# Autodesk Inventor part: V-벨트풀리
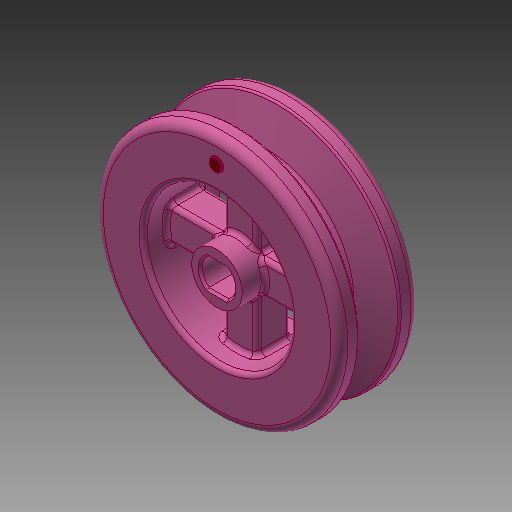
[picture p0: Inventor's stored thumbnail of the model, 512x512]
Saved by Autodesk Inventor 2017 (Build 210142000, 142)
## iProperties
Created: 2018-01
Part Number: V-벨트풀리
Material: 스테인리스강
Document SubType Name: Modeling
Designer: mduedu
Density: 8.08 g/cm^3
Mass: 210.967 g
Surface Area: 122.238 cm^2
Volume: 26.1098 cm^3
Appearance: 분홍색
Author: mduedu
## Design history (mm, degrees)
sketch "스케치1"
  geometry: C1 r 29 at (0, 0); 1 further point
  constraints: 1 centre point, 1 coincident
  dimensions: "d0" = 58 diameter of C1
extrude "돌출1" new body sketch "스케치1" stored distance "d1" = 19; taper "d2" = 0 deg
sketch "스케치2"
  geometry: L1 (29, -9.5)-(-29, -9.5) reference; L2 (-29, -9.5)-(-29, 9.5) reference; L3 (-29, 9.5)-(29, 9.5) reference; L4 (29, 9.5)-(29, -9.5) reference; L5 (-29, 0)-(29, 0); L6 (29, 4.825)-(20, 2.074); L7 (20, 2.074)-(20, -2.074); L8 (20, -2.074)-(29, -4.825); L9 (29, -4.825)-(29, 4.825); L10 (26.3, 9.5)-(26.3, -9.5); L11 (0, -13.3)-(0, 13.3) reference; 4 further points
  constraints: 12 end point, 9 point on line, 3 midpoint, 2 perpendicular, 1 collinear, 1 symmetric about line
  dimensions: "d3" = 34 deg angle of L8 L6; "d4" = 2.7 distance between parallel lines of L10 L4; "d5" = 6.3 distance between parallel lines of L7 L10; "d6" = 8 distance of point (26.3, -4) point (26.3, 4)
revolve "회전1" sketch "스케치2" stored, may be unused: angle "d7" = 90 deg
fillet "모깎기1" dims "d8" = 0.5
fillet "모깎기2" dims "d9" = 1
fillet "모깎기3" dims "d10" = 2
sketch "스케치3"
  geometry: C1 r 17.5 at (0, 0); 1 further point
  constraints: 1 centre point, 1 coincident
  dimensions: "d11" = 35 diameter of C1
extrude "돌출2" cut sketch "스케치3" stored distance "d12" = 19; taper "d13" = 0 deg
sketch "스케치4"
  geometry: C1 r 6 at (0, 0); 1 further point
  constraints: 1 centre point, 1 coincident
  dimensions: "d14" = 12 diameter of C1
extrude "돌출3" join sketch "스케치4" stored distance "d15" = 19; taper "d16" = 0 deg
sketch "스케치5"
  geometry: L1 (0, 6)-(0, 19); L2 (4, 4.472)-(4, 17.037); L3 (4.444, 19.5)-(4.444, 20.524); L4 (-4, 4.472)-(-4, 17.037); L5 (-4.444, 19.5)-(-4.444, 20.524); A1 r 6 centre (0, 0) between (0, 6) and (-4, 4.472) reference; A2 r 17.5 centre (0, 0) between (4, 17.037) and (-4, 17.037) reference; A3 r 20 centre (0, 0) between (4.444, 19.5) and (-4.444, 19.5) reference; 1 further point
  constraints: 10 end point, 7 point on circle, 4 parallel, 1 point on line, 1 vertical, 1 other
  dimensions: "d52" = 8 distance between parallel lines of L2 L4
extrude "돌출4" join sketch "스케치5" stored distance "d18" = 8; taper "d19" = 0 deg
fillet "모깎기4" dims "d20" = 1
fillet "모깎기5" dims "d24" = 1
fillet "모깎기6" dims "d25" = 1
hole "구멍1" diameter "d28" = 8; stored, may be unused: countersink angle "d32" = 90 deg, drill point angle "d34" = 118 deg; dims "d26" = 10, "d27" = 10, "d29" = 6, "d30" = 4, "d31" = 2, "d33" = 8
sketch "스케치6"
  geometry: L1 (-2.332, -3.25)-(2.332, -3.25); L2 (2.332, 3.25)-(-2.332, 3.25); L3 (-2.332, -3.25)-(2.332, 3.25); L4 (2.332, -3.25)-(-2.332, 3.25); A1 r 4 centre (0, 0) between (2.332, 3.25) and (-2.332, 3.25) reference; A2 r 4 centre (0, 0) between (2.332, 3.25) and (-2.332, 3.25); A3 r 4 centre (0, 0) between (-2.332, -3.25) and (2.332, -3.25); 1 further point
  constraints: 8 end point, 7 point on circle, 2 centre point, 2 coincident, 2 midpoint, 1 horizontal, 1 parallel
  dimensions: "d35" = 6.5 distance of L1.end L2.start
extrude "돌출5" join sketch "스케치6" stored distance "d37" = 8; taper "d38" = 0 deg
chamfer "모따기1" distance "d39" = 0.5; stored, may be unused: second distance "d40" = 2, angle "d41" = 45 deg
chamfer "모따기2" distance "d42" = 0.5; stored, may be unused: second distance "d43" = 2, angle "d44" = 45 deg
sketch "스케치7" dims "d45" = 47
  geometry: C1 r 1.5 at (0, 23.5); 2 further points
  constraints: 2 vertical alignment, 1 centre point, 1 coincident, 2 other
  dimensions: "d46" = 3 diameter of C1
extrude "돌출6" join sketch "스케치7" distance "d47" = 0.5; taper "d48" = 0 deg
fillet "모깎기7" dims "d49" = 0.1
node "솔리드1"
pattern_circular "원형 패턴1" dims angle "d22" = 360 deg
node "절단 모서리 투영1"
node "절단 모서리 투영2"
other parameters: "d17" = 8
